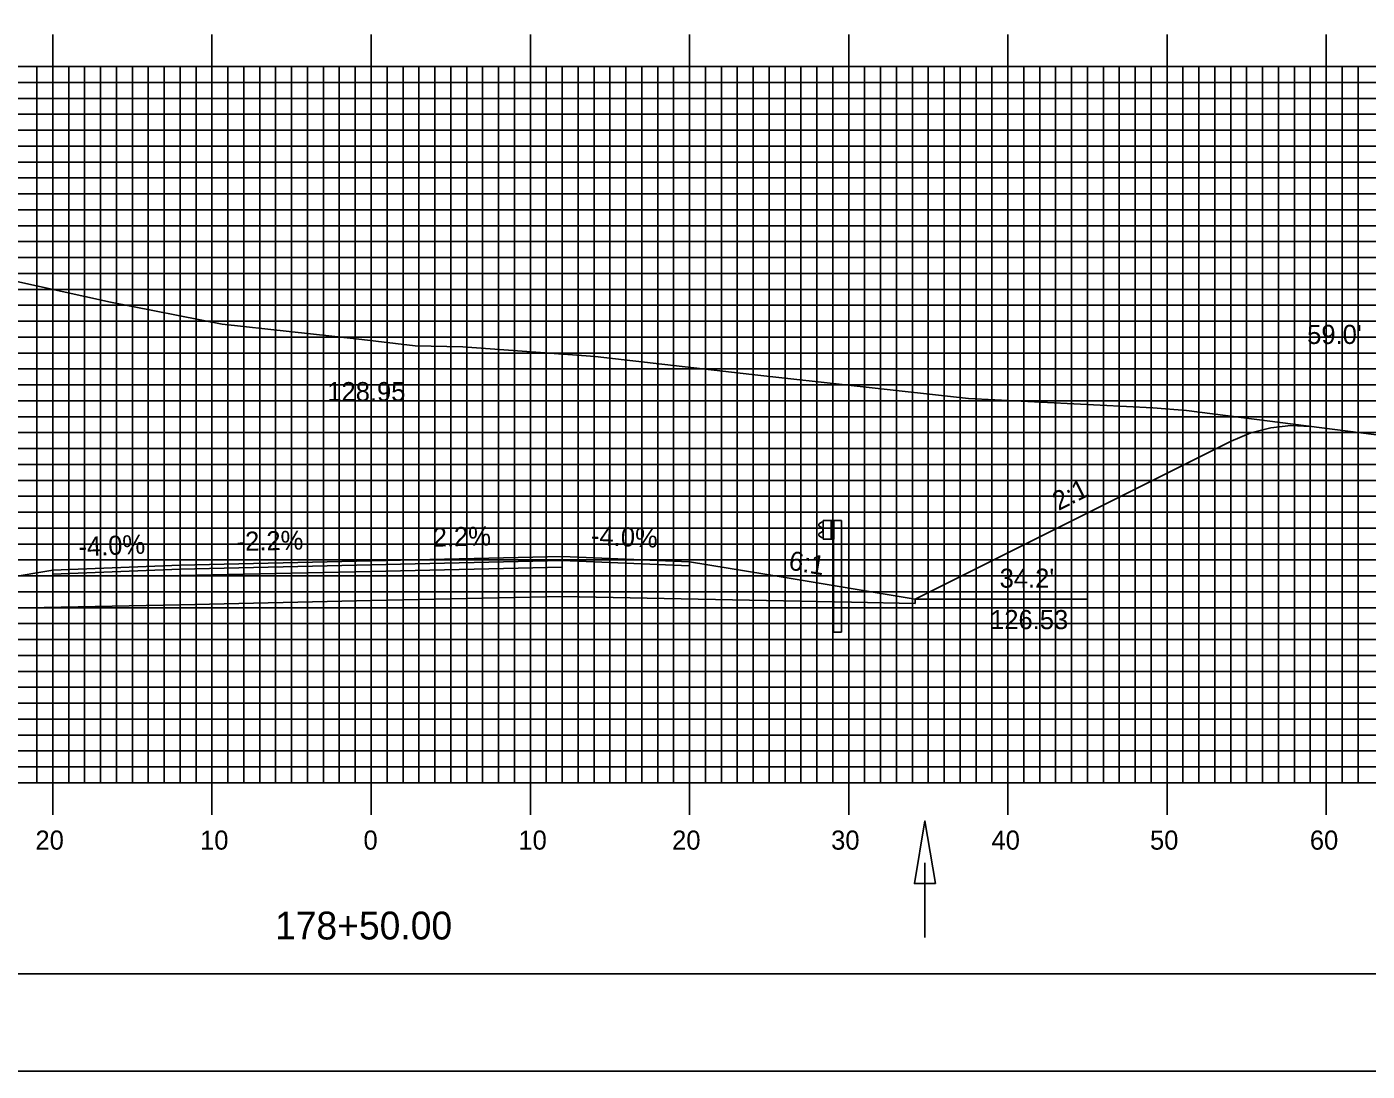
# Model space of a CAD drawing. Extents: x 1785402 to 1785745, y 442591 to 442811.
# Drawn here: x 1785545.9 to 1785630.1, y 442590.5 to 442656.2 of the extents above; entities that cross this region are included whole.
import ezdxf

# ---------------------------------------------------------------- set-up
doc = ezdxf.new("R2010")
doc.units = 0
for name, color, linetype in [('ANNOTATION', 7, 'Continuous'), ('BORDER', 7, 'Continuous'), ('D_Drainage_Ditch_Line', 7, 'Continuous'), ('D_Guardrail_Beam_Rt', 7, 'Continuous'), ('D_Roadway_Centerline', 7, 'Continuous'), ('D_Roadway_Centerline_Text', 7, 'Continuous'), ('D_Roadway_Edge_Shoulder', 7, 'Continuous'), ('D_Roadway_Edge_TW', 7, 'Continuous'), ('D_Roadway_Pavement', 7, 'Continuous'), ('D_Roadway_SlopeLines', 7, 'Continuous'), ('D_Roadway_SubGrade', 7, 'Continuous'), ('D_Text_Standard', 7, 'Continuous'), ('H_V ANNOTATION', 7, 'Continuous'), ('MAJOR', 7, 'Continuous'), ('MINOR', 7, 'Continuous'), ('PDRAIN', 7, 'Continuous'), ('PLOT BOUNDARY', 7, 'Continuous'), ('S_Roadway_Centerline', 7, 'Continuous')]:
    doc.layers.add(name, color=color, linetype=linetype)

msp = doc.modelspace()

# ---------------------------------------------------------------- linework, layer by layer
at = {"layer": 'ANNOTATION'}
for p in [(1785597.713, 442620.011), (1785601.713, 442620.192)]:
    msp.add_line(p, (1785601.713, 442619.931), dxfattribs=at)
msp.add_lwpolyline([(1785587.539, 442622.554), (1785593.539, 442621.554), (1785601.713, 442620.192)], dxfattribs=at)
at = {"layer": 'BORDER'}
msp.add_lwpolyline([(1785417.939, 442596.665), (1785737.939, 442596.665), (1785737.939, 442806.665), (1785417.939, 442806.665)], close=True, dxfattribs=at)
at = {"layer": 'D_Drainage_Ditch_Line'}
msp.add_line((1785602.329, 442603.641), (1785602.329, 442598.942), dxfattribs=at)
msp.add_lwpolyline([(1785602.986, 442602.329), (1785601.673, 442602.329), (1785602.329, 442606.266)], close=True, dxfattribs=at)
at = {"layer": 'D_Guardrail_Beam_Rt'}
for p, q in [((1785595.836, 442625.033), (1785595.692, 442624.933)), ((1785595.926, 442625.054), (1785595.852, 442625.04)), ((1785595.926, 442625.138), (1785596.613, 442625.138)), ((1785595.926, 442623.971), (1785595.926, 442625.138)), ((1785596.447, 442625.138), (1785596.447, 442623.971)), ((1785596.551, 442625.138), (1785596.551, 442623.971)), ((1785596.613, 442625.138), (1785597.084, 442625.138)), ((1785596.613, 442625.138), (1785596.613, 442623.971)), ((1785597.084, 442625.138), (1785597.084, 442618.138)), ((1785595.692, 442624.79), (1785595.888, 442624.654)), ((1785595.888, 442624.455), (1785595.692, 442624.319)), ((1785595.921, 442624.589), (1785595.921, 442624.519)), ((1785595.692, 442624.176), (1785595.836, 442624.076)), ((1785595.852, 442624.069), (1785595.926, 442624.054)), ((1785596.613, 442623.971), (1785595.926, 442623.971)), ((1785596.592, 442618.138), (1785596.592, 442623.971)), ((1785596.592, 442618.138), (1785597.084, 442618.138))]:
    msp.add_line(p, q, dxfattribs=at)
for centre, major_axis, start_param, end_param in [((1785595.86, 442624.999), (-0.0417, 0), 4.907132, 5.323254), ((1785595.743, 442624.861), (-0.0877, 0), 5.323254, 7.243116), ((1785595.743, 442624.247), (-0.0877, 0), 5.323254, 7.243116), ((1785595.842, 442624.589), (0.0789, 0), 0, 0.959931), ((1785595.842, 442624.519), (0.0789, 0), 5.323254, 6.283185), ((1785595.86, 442624.11), (-0.0417, 0), 0.959931, 1.376053)]:
    msp.add_ellipse(centre, major_axis=major_axis, ratio=0.995501, start_param=start_param, end_param=end_param, dxfattribs=at)
at = {"layer": 'D_Roadway_Edge_Shoulder'}
for points in [[(1785579.539, 442622.874), (1785587.539, 442622.554), (1785587.539, 442622.304), (1785579.539, 442622.624)], [(1785555.539, 442622.346), (1785547.539, 442622.026), (1785547.539, 442621.776), (1785555.539, 442622.096)]]:
    msp.add_lwpolyline(points, close=True, dxfattribs=at)
at = {"layer": 'D_Roadway_Edge_TW'}
msp.add_lwpolyline([(1785555.539, 442622.096), (1785555.539, 442622.346), (1785567.539, 442622.61), (1785579.539, 442622.874), (1785579.539, 442622.624), (1785567.539, 442622.36)], close=True, dxfattribs=at)
at = {"layer": 'D_Roadway_Pavement'}
msp.add_lwpolyline([(1785555.539, 442621.68), (1785555.539, 442622.096), (1785567.539, 442622.36), (1785579.539, 442622.624), (1785579.539, 442622.208), (1785567.539, 442621.944)], close=True, dxfattribs=at)
at = {"layer": 'D_Roadway_SlopeLines'}
for points in [[(1785601.713, 442620.192), (1785621.562, 442630.117), (1785622.812, 442630.644), (1785624.062, 442630.974), (1785625.312, 442631.109), (1785626.562, 442631.047)], [(1785547.539, 442622.026), (1785541.539, 442621.026), (1785533.365, 442619.664)]]:
    msp.add_lwpolyline(points, dxfattribs=at)
at = {"layer": 'D_Roadway_SubGrade'}
for points in [[(1785547.539, 442622.026), (1785547.539, 442621.776), (1785555.539, 442622.096), (1785567.539, 442622.36), (1785579.539, 442622.624), (1785587.539, 442622.304), (1785587.539, 442622.554)], [(1785597.713, 442620.011), (1785579.539, 442620.374), (1785567.539, 442620.11), (1785555.539, 442619.846), (1785537.365, 442619.483)]]:
    msp.add_lwpolyline(points, dxfattribs=at)
at = {"layer": 'MAJOR'}
for p, q in [((1785547.539, 442655.669), (1785547.539, 442653.665)), ((1785557.539, 442655.669), (1785557.539, 442653.665)), ((1785567.539, 442655.669), (1785567.539, 442653.665)), ((1785577.539, 442655.669), (1785577.539, 442653.665)), ((1785587.539, 442655.669), (1785587.539, 442653.665)), ((1785597.539, 442655.669), (1785597.539, 442653.665)), ((1785607.539, 442655.669), (1785607.539, 442653.665)), ((1785617.539, 442655.669), (1785617.539, 442653.665)), ((1785627.539, 442655.669), (1785627.539, 442653.665)), ((1785427.539, 442653.665), (1785707.539, 442653.665)), ((1785427.539, 442653.665), (1785707.539, 442653.665)), ((1785547.539, 442608.665), (1785547.539, 442653.665)), ((1785557.539, 442608.665), (1785557.539, 442653.665)), ((1785567.539, 442608.665), (1785567.539, 442653.665)), ((1785577.539, 442608.665), (1785577.539, 442653.665)), ((1785587.539, 442608.665), (1785587.539, 442653.665)), ((1785597.539, 442608.665), (1785597.539, 442653.665)), ((1785607.539, 442608.665), (1785607.539, 442653.665)), ((1785617.539, 442608.665), (1785617.539, 442653.665)), ((1785627.539, 442608.665), (1785627.539, 442653.665)), ((1785427.539, 442648.665), (1785707.539, 442648.665)), ((1785427.539, 442643.665), (1785707.539, 442643.665)), ((1785427.539, 442638.665), (1785707.539, 442638.665)), ((1785427.539, 442633.665), (1785707.539, 442633.665)), ((1785427.539, 442628.665), (1785707.539, 442628.665)), ((1785427.539, 442623.665), (1785707.539, 442623.665)), ((1785427.539, 442618.665), (1785707.539, 442618.665)), ((1785427.539, 442613.665), (1785707.539, 442613.665)), ((1785427.539, 442608.665), (1785707.539, 442608.665)), ((1785427.539, 442608.665), (1785707.539, 442608.665)), ((1785547.539, 442606.661), (1785547.539, 442608.665)), ((1785557.539, 442606.661), (1785557.539, 442608.665)), ((1785567.539, 442606.661), (1785567.539, 442608.665)), ((1785577.539, 442606.661), (1785577.539, 442608.665)), ((1785587.539, 442606.661), (1785587.539, 442608.665)), ((1785597.539, 442606.661), (1785597.539, 442608.665)), ((1785607.539, 442606.661), (1785607.539, 442608.665)), ((1785617.539, 442606.661), (1785617.539, 442608.665)), ((1785627.539, 442606.661), (1785627.539, 442608.665))]:
    msp.add_line(p, q, dxfattribs=at)
at = {"layer": 'MINOR'}
for p, q in [((1785546.539, 442608.665), (1785546.539, 442653.665)), ((1785548.539, 442608.665), (1785548.539, 442653.665)), ((1785549.539, 442608.665), (1785549.539, 442653.665)), ((1785550.539, 442608.665), (1785550.539, 442653.665)), ((1785551.539, 442608.665), (1785551.539, 442653.665)), ((1785552.539, 442608.665), (1785552.539, 442653.665)), ((1785553.539, 442608.665), (1785553.539, 442653.665)), ((1785554.539, 442608.665), (1785554.539, 442653.665)), ((1785555.539, 442608.665), (1785555.539, 442653.665)), ((1785556.539, 442608.665), (1785556.539, 442653.665)), ((1785558.539, 442608.665), (1785558.539, 442653.665)), ((1785559.539, 442608.665), (1785559.539, 442653.665)), ((1785560.539, 442608.665), (1785560.539, 442653.665)), ((1785561.539, 442608.665), (1785561.539, 442653.665)), ((1785562.539, 442608.665), (1785562.539, 442653.665)), ((1785563.539, 442608.665), (1785563.539, 442653.665)), ((1785564.539, 442608.665), (1785564.539, 442653.665)), ((1785565.539, 442608.665), (1785565.539, 442653.665)), ((1785566.539, 442608.665), (1785566.539, 442653.665)), ((1785568.539, 442608.665), (1785568.539, 442653.665)), ((1785569.539, 442608.665), (1785569.539, 442653.665)), ((1785570.539, 442608.665), (1785570.539, 442653.665)), ((1785571.539, 442608.665), (1785571.539, 442653.665)), ((1785572.539, 442608.665), (1785572.539, 442653.665)), ((1785573.539, 442608.665), (1785573.539, 442653.665)), ((1785574.539, 442608.665), (1785574.539, 442653.665)), ((1785575.539, 442608.665), (1785575.539, 442653.665)), ((1785576.539, 442608.665), (1785576.539, 442653.665)), ((1785578.539, 442608.665), (1785578.539, 442653.665)), ((1785579.539, 442608.665), (1785579.539, 442653.665)), ((1785580.539, 442608.665), (1785580.539, 442653.665)), ((1785581.539, 442608.665), (1785581.539, 442653.665)), ((1785582.539, 442608.665), (1785582.539, 442653.665)), ((1785583.539, 442608.665), (1785583.539, 442653.665)), ((1785584.539, 442608.665), (1785584.539, 442653.665)), ((1785585.539, 442608.665), (1785585.539, 442653.665)), ((1785586.539, 442608.665), (1785586.539, 442653.665)), ((1785588.539, 442608.665), (1785588.539, 442653.665)), ((1785589.539, 442608.665), (1785589.539, 442653.665)), ((1785590.539, 442608.665), (1785590.539, 442653.665)), ((1785591.539, 442608.665), (1785591.539, 442653.665)), ((1785592.539, 442608.665), (1785592.539, 442653.665)), ((1785593.539, 442608.665), (1785593.539, 442653.665)), ((1785594.539, 442608.665), (1785594.539, 442653.665)), ((1785595.539, 442608.665), (1785595.539, 442653.665)), ((1785596.539, 442608.665), (1785596.539, 442653.665)), ((1785598.539, 442608.665), (1785598.539, 442653.665)), ((1785599.539, 442608.665), (1785599.539, 442653.665)), ((1785600.539, 442608.665), (1785600.539, 442653.665)), ((1785601.539, 442608.665), (1785601.539, 442653.665)), ((1785602.539, 442608.665), (1785602.539, 442653.665)), ((1785603.539, 442608.665), (1785603.539, 442653.665)), ((1785604.539, 442608.665), (1785604.539, 442653.665)), ((1785605.539, 442608.665), (1785605.539, 442653.665)), ((1785606.539, 442608.665), (1785606.539, 442653.665)), ((1785608.539, 442608.665), (1785608.539, 442653.665)), ((1785609.539, 442608.665), (1785609.539, 442653.665)), ((1785610.539, 442608.665), (1785610.539, 442653.665)), ((1785611.539, 442608.665), (1785611.539, 442653.665)), ((1785612.539, 442608.665), (1785612.539, 442653.665)), ((1785613.539, 442608.665), (1785613.539, 442653.665)), ((1785614.539, 442608.665), (1785614.539, 442653.665)), ((1785615.539, 442608.665), (1785615.539, 442653.665)), ((1785616.539, 442608.665), (1785616.539, 442653.665)), ((1785618.539, 442608.665), (1785618.539, 442653.665)), ((1785619.539, 442608.665), (1785619.539, 442653.665)), ((1785620.539, 442608.665), (1785620.539, 442653.665)), ((1785621.539, 442608.665), (1785621.539, 442653.665)), ((1785622.539, 442608.665), (1785622.539, 442653.665)), ((1785623.539, 442608.665), (1785623.539, 442653.665)), ((1785624.539, 442608.665), (1785624.539, 442653.665)), ((1785625.539, 442608.665), (1785625.539, 442653.665)), ((1785626.539, 442608.665), (1785626.539, 442653.665)), ((1785628.539, 442608.665), (1785628.539, 442653.665)), ((1785629.539, 442608.665), (1785629.539, 442653.665)), ((1785427.539, 442652.665), (1785707.539, 442652.665)), ((1785427.539, 442651.665), (1785707.539, 442651.665)), ((1785427.539, 442650.665), (1785707.539, 442650.665)), ((1785427.539, 442649.665), (1785707.539, 442649.665)), ((1785427.539, 442647.665), (1785707.539, 442647.665)), ((1785427.539, 442646.665), (1785707.539, 442646.665)), ((1785427.539, 442645.665), (1785707.539, 442645.665)), ((1785427.539, 442644.665), (1785707.539, 442644.665)), ((1785427.539, 442642.665), (1785707.539, 442642.665)), ((1785427.539, 442641.665), (1785707.539, 442641.665)), ((1785427.539, 442640.665), (1785707.539, 442640.665)), ((1785427.539, 442639.665), (1785707.539, 442639.665)), ((1785427.539, 442637.665), (1785707.539, 442637.665)), ((1785427.539, 442636.665), (1785707.539, 442636.665)), ((1785427.539, 442635.665), (1785707.539, 442635.665)), ((1785427.539, 442634.665), (1785707.539, 442634.665)), ((1785427.539, 442632.665), (1785707.539, 442632.665)), ((1785427.539, 442631.665), (1785707.539, 442631.665)), ((1785427.539, 442630.665), (1785707.539, 442630.665)), ((1785427.539, 442629.665), (1785707.539, 442629.665)), ((1785427.539, 442627.665), (1785707.539, 442627.665)), ((1785427.539, 442626.665), (1785707.539, 442626.665)), ((1785427.539, 442625.665), (1785707.539, 442625.665)), ((1785427.539, 442624.665), (1785707.539, 442624.665)), ((1785427.539, 442622.665), (1785707.539, 442622.665)), ((1785427.539, 442621.665), (1785707.539, 442621.665)), ((1785427.539, 442620.665), (1785707.539, 442620.665)), ((1785427.539, 442619.665), (1785707.539, 442619.665)), ((1785427.539, 442617.665), (1785707.539, 442617.665)), ((1785427.539, 442616.665), (1785707.539, 442616.665)), ((1785427.539, 442615.665), (1785707.539, 442615.665)), ((1785427.539, 442614.665), (1785707.539, 442614.665)), ((1785427.539, 442612.665), (1785707.539, 442612.665)), ((1785427.539, 442611.665), (1785707.539, 442611.665)), ((1785427.539, 442610.665), (1785707.539, 442610.665)), ((1785427.539, 442609.665), (1785707.539, 442609.665))]:
    msp.add_line(p, q, dxfattribs=at)
at = {"layer": 'PDRAIN'}
msp.add_line((1785601.713, 442620.192), (1785612.484, 442620.192), dxfattribs=at)
at = {"layer": 'PLOT BOUNDARY'}
msp.add_lwpolyline([(1785401.752, 442590.547), (1785741.752, 442590.547), (1785741.752, 442810.547), (1785401.752, 442810.547)], close=True, dxfattribs=at)
at = {"layer": 'S_Roadway_Centerline'}
msp.add_lwpolyline([(1785497.479, 442645.683), (1785499.856, 442645.596), (1785501.884, 442645.516), (1785509.048, 442645.898), (1785514.183, 442645.757), (1785520.193, 442644.952), (1785523.4, 442644.568), (1785530.676, 442643.698), (1785535.581, 442642.292), (1785551.168, 442638.855), (1785558.17, 442637.488), (1785566.606, 442636.557), (1785570.297, 442636.11), (1785573.3, 442636.061), (1785581.609, 442635.454), (1785591.458, 442634.321), (1785605.073, 442632.799), (1785616.645, 442632.213), (1785618.76, 442632.045), (1785638.221, 442629.555)], dxfattribs=at)

# ---------------------------------------------------------------- texts
at = {"layer": 'ANNOTATION'}
for s, rotation, p in [('2:1', 26.56505, (1785610.723, 442625.733)), ('-4.0%', 2.29061, (1785549.171, 442622.893)), ('-2.2%', 1.2603, (1785559.098, 442623.225)), ('2.2%', 1.2603, (1785571.419, 442623.496)), ('-4.0%', 357.70939, (1785581.33, 442623.604)), ('6:1', 350.53768, (1785593.718, 442622.066))]:
    msp.add_text(s, height=1.2, rotation=rotation, dxfattribs=at).set_placement(p)
for s, p in [("34.2'", (1785607.023, 442620.918)), ('126.53', (1785606.423, 442618.318))]:
    msp.add_text(s, height=1.2, dxfattribs=at).set_placement(p)
at = {"layer": 'D_Roadway_Centerline'}
for s, p in [('C', (1785567.533, 442622.61)), ('L', (1785567.539, 442622.603))]:
    msp.add_text(s, height=0.0146, dxfattribs=at).set_placement(p)
at = {"layer": 'D_Roadway_Centerline_Text'}
msp.add_text('128.95', height=1.2, dxfattribs=at).set_placement((1785564.783, 442632.64))
at = {"layer": 'D_Text_Standard'}
msp.add_text("59.0'", height=1.2, dxfattribs=at).set_placement((1785626.342, 442636.233))
at = {"layer": 'H_V ANNOTATION'}
for s, height, p in [('20', 1.2, (1785546.447, 442604.465)), ('10', 1.2, (1785556.789, 442604.465)), ('0', 1.2, (1785567.057, 442604.465)), ('10', 1.2, (1785576.789, 442604.465)), ('20', 1.2, (1785586.447, 442604.465)), ('30', 1.2, (1785596.436, 442604.465)), ('40', 1.2, (1785606.511, 442604.465)), ('50', 1.2, (1785616.468, 442604.465)), ('60', 1.2, (1785626.511, 442604.465)), ('178+50.00', 1.75, (1785561.499, 442598.821))]:
    msp.add_text(s, height=height, dxfattribs=at).set_placement(p)

doc.saveas('drawing.dxf')
